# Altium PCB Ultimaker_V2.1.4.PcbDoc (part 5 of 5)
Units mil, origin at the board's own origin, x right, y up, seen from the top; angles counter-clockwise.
Board outline 6889.76 x 3110.24 mil, 4 copper layers (top, signal, Power, bot (thermal)), stack 67.717 mil thick; 574 components, 252 nets, 1322 pads, 511 vias.
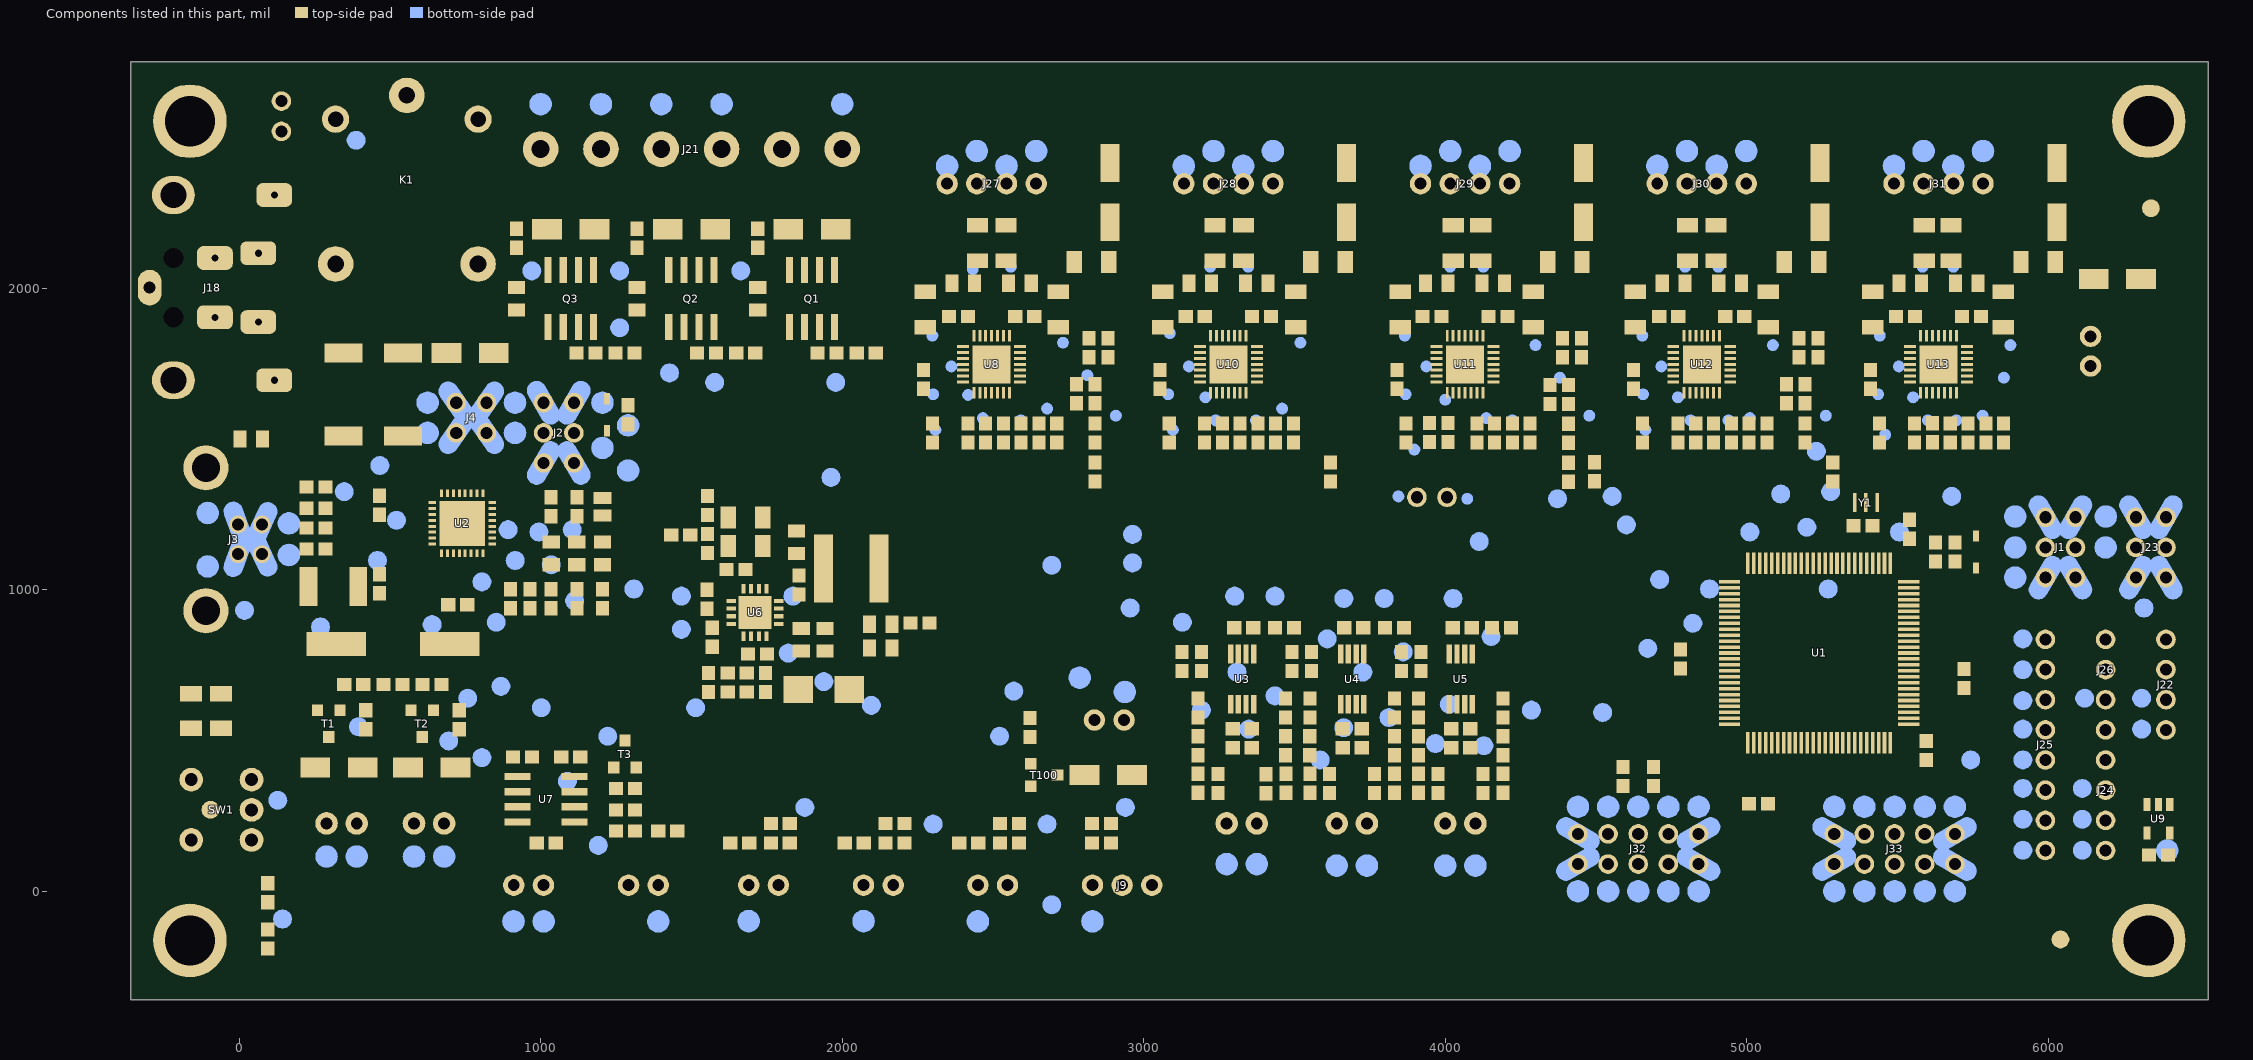
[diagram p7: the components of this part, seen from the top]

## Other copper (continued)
Power:
  rectangle net +5V: 5885.64,1527.39 5955.64,1577.39
  rectangle net +5V: 5100.64,1527.39 5170.64,1577.39
  rectangle net +5V: 4315.64,1527.39 4385.64,1577.39
  rectangle net +5V: 3530.64,1527.39 3600.64,1577.39
  rectangle net +5V: 2740.64,1527.39 2810.64,1577.39
  rectangle net +5V: 2161.66,656.84 2327.01,790.7
  pour cut-out: 4525.63,1332.39 4525.64,2312.39 5060.64,2312.39 5060.64,2492.39 5290.64,2492.39 5290.64,2337.39 5170.64,2337.39 5170.64,1942.39 5255.64,1942.39 5255.64,1577.39 5150.63,1577.39 5150.63,1527.39 5165.63,1527.39 5165.63,1332.39
  pour cut-out: 3740.63,1332.39 3740.64,2312.39 4275.64,2312.39 4275.64,2492.39 4505.64,2492.39 4505.64,2337.39 4385.64,2337.39 4385.64,1942.39 4470.64,1942.39 4470.64,1577.39 4365.63,1577.39 4365.63,1527.39 4380.63,1527.39 4380.63,1332.39
  pour cut-out: 2955.63,1332.39 2955.64,2312.39 3490.64,2312.39 3490.64,2492.39 3720.64,2492.39 3720.64,2337.39 3600.64,2337.39 3600.64,1978.63 3610.24,1956.69 3610.24,1578.74 3580.63,1577.39 3580.63,1527.39 3595.63,1527.39 3595.63,1332.39
  pour cut-out: 2170.64,1332.39 2170.64,2312.39 2705.64,2312.39 2705.64,2492.39 2935.64,2492.39 2935.64,2337.39 2815.64,2337.39 2815.64,1942.39 2900.64,1942.39 2900.64,1577.39 2795.64,1577.39 2795.64,1527.39 2810.64,1527.39 2810.64,1332.39
  region net GND: 3221.64,1927.39 3221.64,1813.39 3355.64,1813.39 3355.64,1802.39 3435.28,1801.42 3434.64,1663.39 3476.64,1663.39 3478.58,1789.61 3502.2,1789.61 3502.2,1836.85 3466.77,1836.85 3435.28,1801.42 3355.64,1802.39 3355.64,1813.39 3339.64,1813.39 3339.64,1928.39 3506.63,1928.39 3506.63,2477.39 3705.64,2477.39 3705.64,2352.39 3585.64,2352.39 3585.64,1592.39 3442.64,1592.39 3443.15,1612.44 3411.65,1643.94 3309.29,1643.94 3289.61,1628.19 3179.37,1628.19 3179.37,1580.94 3155.75,1557.32 3112.44,1557.32 3112.44,1510.08 3155.75,1510.08 3155.75,1557.32 3179.37,1580.94 3442.64,1579.39 3442.64,1592.39 3515.64,1592.39 3515.64,1512.39 3580.64,1512.39 3580.64,1347.39 3224.64,1347.39 3224.64,1419.39 3462.64,1419.39 3462.64,1464.39 3224.64,1464.39 3224.64,1347.39 2970.64,1347.39 2970.63,2146.39 2970.64,2297.39 3063.64,2297.39 3063.63,2293.39 3063.63,1814.39 2994.64,1814.39 2994.64,1757.39 3063.64,1757.39 3063.64,1583.39 3105.64,1583.39 3104.57,1643.94 3136.06,1643.94 3136.06,1828.98 3104.57,1860.47 3104.57,1927.4
  region net GND: 2436.64,1927.39 2436.64,1813.39 2570.64,1813.39 2570.64,1793.39 2642.64,1793.39 2642.64,1681.39 2686.64,1681.39 2686.64,1707.39 2799.64,1707.39 2799.64,1747.39 2755.64,1747.39 2755.64,1707.39 2686.64,1707.39 2687.24,1789.61 2718.74,1789.61 2718.74,1836.85 2687.24,1836.85 2643.94,1793.54 2570.64,1793.39 2570.64,1813.39 2554.64,1813.39 2554.64,1927.39 2721.64,1927.39 2721.64,2477.39 2920.64,2477.39 2920.64,2352.39 2800.64,2352.39 2800.64,1927.39 2885.64,1927.39 2885.64,1592.39 2658.64,1592.39 2659.69,1616.38 2632.13,1643.94 2525.83,1643.94 2506.14,1628.19 2395.91,1628.19 2395.91,1577.01 2372.28,1557.32 2325.04,1557.32 2325.04,1510.08 2372.28,1510.08 2372.28,1557.32 2395.91,1577.01 2659.69,1577.01 2658.64,1592.39 2725.64,1592.39 2725.64,1512.39 2795.64,1512.39 2795.64,1347.39 2439.64,1347.39 2439.64,1419.39 2677.64,1419.39 2677.64,1464.39 2439.64,1464.39 2439.64,1347.39 2185.64,1347.39 2185.64,2297.39 2278.64,2297.39 2278.63,1814.39 2209.64,1814.39 2209.64,1757.39 2278.64,1757.39 2278.64,1584.39 2320.64,1584.39 2321.1,1643.94 2352.6,1643.94 2352.6,1828.98 2321.1,1856.54 2320.64,1927.39
  region net GND: 4791.64,1927.39 4791.64,1813.39 4925.64,1813.39 4925.64,1793.39 4997.64,1793.39 4997.64,1681.39 5041.64,1681.39 5041.64,1707.39 5154.64,1707.39 5154.63,1748.39 5110.63,1748.39 5110.64,1707.39 5041.64,1707.39 5041.57,1789.61 5073.07,1789.61 5073.07,1836.85 5037.64,1836.85 4998.27,1793.54 4925.64,1793.39 4925.64,1813.39 4909.64,1813.39 4909.64,1928.39 5076.63,1928.39 5076.63,2477.39 5275.64,2477.39 5275.64,2352.39 5155.64,2352.39 5155.64,1927.39 5240.64,1927.39 5240.64,1592.39 5084.88,1592.76 5014.02,1592.76 5014.02,1612.44 5010.08,1616.38 4982.52,1643.94 4868.35,1643.94 4844.72,1628.19 4750.24,1628.19 4750.24,1577.01 5014.02,1577.01 5014.02,1592.76 5084.88,1592.76 5085.64,1512.39 5150.64,1512.39 5151.64,1347.39 4794.64,1347.39 4794.64,1419.39 5032.64,1419.39 5032.64,1464.39 4794.64,1464.39 4794.64,1347.39 4540.64,1347.39 4540.63,2146.39 4540.64,2297.39 4633.64,2297.39 4633.63,1814.39 4564.64,1814.39 4564.64,1757.39 4633.64,1757.39 4633.64,1584.39 4675.43,1584.88 4679.37,1557.32 4679.37,1510.08 4726.61,1510.08 4726.61,1557.32 4679.37,1557.32 4675.43,1584.88 4675.43,1643.94 4706.93,1643.94 4706.93,1828.98 4675.43,1860.47 4675.64,1927.39
  pour cut-out: 5310.63,1374.16 5310.64,2312.39 5845.64,2312.39 5845.64,2492.39 6075.64,2492.39 6075.64,2337.39 5955.64,2337.39 5955.64,1942.39 6040.64,1942.39 6040.64,1577.39 5935.63,1577.39 5935.63,1527.39 5950.63,1527.39 5950.63,1332.39 5417.56,1334.01 5417.56,1373.38
  region net GND: 4006.64,1927.39 4006.64,1813.39 4140.64,1813.39 4140.64,1793.39 4212.64,1793.39 4212.64,1681.39 4256.64,1681.39 4256.64,1707.39 4369.64,1707.39 4369.63,1748.39 4325.63,1748.39 4325.64,1707.39 4256.64,1707.39 4258.11,1789.61 4285.67,1789.61 4285.67,1836.85 4242.36,1836.85 4242.36,1793.54 4140.64,1793.39 4140.64,1813.39 4124.64,1813.39 4124.64,1928.39 4291.63,1928.39 4291.63,2477.39 4490.64,2477.39 4490.64,2352.39 4370.64,2352.39 4370.64,1927.39 4455.64,1927.39 4455.64,1592.39 4226.64,1592.39 4226.61,1608.5 4191.18,1643.94 4124.25,1643.94 4100.63,1620.31 3974.65,1620.31 3974.65,1573.07 4029.76,1573.07 4029.76,1514.02 4082.92,1515.11 4082.92,1574.17 4224.65,1574.17 4226.64,1578.39 4226.64,1592.39 4300.64,1592.39 4300.64,1512.39 4365.64,1512.39 4366.64,1347.39 3984.49,1349.76 3984.25,1417.32 4248.03,1417.32 4247.64,1464.39 3846.46,1464.57 3846.46,1417.32 3893.7,1417.32 3893.7,1464.57 3984.25,1464.57 3984.49,1349.76 3755.64,1347.39 3755.63,2146.39 3755.64,2297.39 3848.64,2297.39 3848.63,1814.39 3779.64,1814.39 3779.64,1757.39 3848.64,1757.39 3848.64,1584.39 3890.64,1584.39 3891.97,1643.94 3919.53,1643.94 3919.53,1832.91 3891.97,1856.54 3890.64,1927.39
  region net GND: 5576.64,1927.39 5576.64,1813.39 5710.64,1813.39 5710.64,1793.39 5762.05,1797.48 5762.05,1750.24 5789.61,1750.24 5791.58,1656.84 5838.82,1656.84 5838.82,1751.33 5827.01,1751.33 5813.23,1765.98 5813.23,1789.61 5856.54,1789.61 5856.54,1836.85 5821.1,1836.85 5781.73,1797.48 5762.05,1797.48 5710.64,1793.39 5710.64,1813.39 5694.64,1813.39 5694.64,1928.39 5861.63,1928.39 5861.63,2477.39 6060.64,2477.39 6060.64,2352.39 5940.64,2352.39 5940.64,1927.39 6025.64,1927.39 6025.64,1592.39 5773.86,1592.76 5773.86,1608.5 5738.43,1643.94 5663.62,1643.94 5647.87,1628.19 5533.7,1628.19 5533.7,1580.94 5625.64,1578.39 5773.86,1577.01 5773.86,1592.76 5872.28,1592.76 5872.28,1514.02 5935.64,1512.39 5936.64,1347.39 5578.98,1345.82 5579.64,1419.39 5817.64,1419.39 5817.64,1464.39 5579.64,1464.39 5578.98,1345.82 5429.37,1345.82 5429.37,1385.19 5327.01,1385.19 5325.63,2146.39 5325.64,2297.39 5418.64,2297.39 5418.63,1814.39 5349.64,1814.39 5349.64,1757.39 5418.64,1757.39 5418.64,1584.39 5466.77,1584.88 5466.77,1510.08 5510.08,1510.08 5510.08,1557.32 5466.77,1557.32 5466.77,1643.94 5490.39,1643.94 5490.39,1828.98 5462.83,1864.41 5462.83,1927.4
  pour cut-out: 792.44,2155 ccw(c792.44,2080) 717.44,2080 ccw(c792.44,2080) 792.44,2005 ccw(c792.44,2080) 867.44,2080 ccw(c792.44,2080)
  pour cut-out: 556.22,2714.06 ccw(c556.22,2639.06) 481.22,2639.06 ccw(c556.22,2639.06) 556.22,2564.06 ccw(c556.22,2639.06) 631.22,2639.06 ccw(c556.22,2639.06)
  pour cut-out: 1000,2536 ccw(c1000,2461) 925,2461 ccw(c1000,2461) 1000,2386 ccw(c1000,2461) 1075,2461 ccw(c1000,2461)
  pour cut-out: 1200,2536 ccw(c1200,2461) 1125,2461 ccw(c1200,2461) 1200,2386 ccw(c1200,2461) 1275,2461 ccw(c1200,2461)
  pour cut-out: 1400,2536 ccw(c1400,2461) 1325,2461 ccw(c1400,2461) 1400,2386 ccw(c1400,2461) 1475,2461 ccw(c1400,2461)
  pour cut-out: 1600,2536 ccw(c1600,2461) 1525,2461 ccw(c1600,2461) 1600,2386 ccw(c1600,2461) 1675,2461 ccw(c1600,2461)
  pour cut-out: 2000,2536 ccw(c2000,2461) 1925,2461 ccw(c2000,2461) 2000,2386 ccw(c2000,2461) 2075,2461 ccw(c2000,2461)
  pour cut-out: 1800,2536 ccw(c1800,2461) 1725,2461 ccw(c1800,2461) 1800,2386 ccw(c1800,2461) 1875,2461 ccw(c1800,2461)
  pour cut-out: -160,1908.15 cw(c-60,1908.15) -60,2008.15 165,2008.15 215,2058.15 215,2088.15 cw(c315,2088.15) 315,2188.15 325,2188.15 cw(c325,2088.15) 425,2088.15 425,2001.43 cw(c356.72,2001.43) 405,1953.15 279.29,1827.44 cw(c208.58,1898.15) 208.58,1798.15 -60,1798.15 cw(c-60,1898.15) -160,1898.15
  text "Copper inner2 35u" at -300,3285 h196.85
bot (thermal):
  rectangle net GND: 2426.93,1677.17 2566.93,1817.17
  rectangle net GND: 3210.63,1676.53 3350.63,1816.53
  rectangle net GND: 3997.8,1677.17 4137.8,1817.17
  rectangle net GND: 4781.26,1677.17 4921.26,1817.17
  rectangle net GND: 669,1151 810,1289
  rectangle net GND: 5564.72,1677.17 5704.72,1817.17
  region net GND: 1795,1975 1955,1975 1955,1915 1795,1915
  region net GND: 1395,1975 1555,1975 1555,1915 1395,1915
  region net GND: 995,1975 1155,1975 1155,1915 995,1915
  region net GND: -150,2170 135,2170 135,2050 -150,2050
  pour cut-out: 5346.46,1887.27 ccw(c5346.46,1858.27) 5317.46,1858.27 ccw(c5346.46,1858.27) 5346.46,1829.27 ccw(c5346.46,1858.27) 5375.46,1858.27 ccw(c5346.46,1858.27)
  pour cut-out: 5346.46,1997.5 ccw(c5346.46,1968.5) 5317.46,1968.5 ccw(c5346.46,1968.5) 5346.46,1939.5 ccw(c5346.46,1968.5) 5375.46,1968.5 ccw(c5346.46,1968.5)
  pour cut-out: 5137.8,1926.64 ccw(c5137.8,1897.64) 5108.8,1897.64 ccw(c5137.8,1897.64) 5137.8,1868.64 ccw(c5137.8,1897.64) 5166.8,1897.64 ccw(c5137.8,1897.64)
  pour cut-out: 4562.99,1887.27 ccw(c4562.99,1858.27) 4533.99,1858.27 ccw(c4562.99,1858.27) 4562.99,1829.27 ccw(c4562.99,1858.27) 4591.99,1858.27 ccw(c4562.99,1858.27)
  pour cut-out: 4562.99,1993.57 ccw(c4562.99,1964.57) 4533.99,1964.57 ccw(c4562.99,1964.57) 4562.99,1935.57 ccw(c4562.99,1964.57) 4591.99,1964.57 ccw(c4562.99,1964.57)
  pour cut-out: 4358.27,1926.64 ccw(c4358.27,1897.64) 4329.27,1897.64 ccw(c4358.27,1897.64) 4358.27,1868.64 ccw(c4358.27,1897.64) 4387.27,1897.64 ccw(c4358.27,1897.64)
  pour cut-out: 3779.53,1887.27 ccw(c3779.53,1858.27) 3750.53,1858.27 ccw(c3779.53,1858.27) 3779.53,1829.27 ccw(c3779.53,1858.27) 3808.53,1858.27 ccw(c3779.53,1858.27)
  pour cut-out: 3783.46,2005.38 ccw(c3783.46,1976.38) 3754.46,1976.38 ccw(c3783.46,1976.38) 3783.46,1947.38 ccw(c3783.46,1976.38) 3812.46,1976.38 ccw(c3783.46,1976.38)
  pour cut-out: 3574.44,1925.39 ccw(c3574.44,1896.39) 3545.44,1896.39 ccw(c3574.44,1896.39) 3574.44,1867.39 ccw(c3574.44,1896.39) 3603.44,1896.39 ccw(c3574.44,1896.39)
  pour cut-out: 2992.13,1997.5 ccw(c2992.13,1968.5) 2963.13,1968.5 ccw(c2992.13,1968.5) 2992.13,1939.5 ccw(c2992.13,1968.5) 3021.13,1968.5 ccw(c2992.13,1968.5)
  pour cut-out: 2992.13,1887.27 ccw(c2992.13,1858.27) 2963.13,1858.27 ccw(c2992.13,1858.27) 2992.13,1829.27 ccw(c2992.13,1858.27) 3021.13,1858.27 ccw(c2992.13,1858.27)
  pour cut-out: 2791.34,1926.64 ccw(c2791.34,1897.64) 2762.34,1897.64 ccw(c2791.34,1897.64) 2791.34,1868.64 ccw(c2791.34,1897.64) 2820.34,1897.64 ccw(c2791.34,1897.64)
  pour cut-out: 2205.95,1888.39 ccw(c2205.95,1859.39) 2176.95,1859.39 ccw(c2205.95,1859.39) 2205.95,1830.39 ccw(c2205.95,1859.39) 2234.95,1859.39 ccw(c2205.95,1859.39)
  pour cut-out: 2205.95,1996.15 ccw(c2205.95,1967.15) 2176.95,1967.15 ccw(c2205.95,1967.15) 2205.95,1938.15 ccw(c2205.95,1967.15) 2234.95,1967.15 ccw(c2205.95,1967.15)
  pour cut-out: -160,1908.15 cw(c-60,1908.15) -60,2008.15 165,2008.15 215,2058.15 215,2088.15 cw(c315,2088.15) 315,2188.15 325,2188.15 cw(c325,2088.15) 425,2088.15 425,2001.43 cw(c356.72,2001.43) 405,1953.15 279.29,1827.44 cw(c208.58,1898.15) 208.58,1798.15 -60,1798.15 cw(c-60,1898.15) -160,1898.15
  pour cut-out: 556.22,2714.06 ccw(c556.22,2639.06) 481.22,2639.06 ccw(c556.22,2639.06) 556.22,2564.06 ccw(c556.22,2639.06) 631.22,2639.06 ccw(c556.22,2639.06)
  pour cut-out: 925,2461 ccw(c1000,2461) 1000,2386 ccw(c1000,2461) 1075,2461 1075,2591 ccw(c1000,2591) 1000,2666 ccw(c1000,2591) 925,2591
  pour cut-out: 1125,2461 ccw(c1200,2461) 1200,2386 ccw(c1200,2461) 1275,2461 1275,2591 ccw(c1200,2591) 1200,2666 ccw(c1200,2591) 1125,2591
  pour cut-out: 1325,2461 ccw(c1400,2461) 1400,2386 ccw(c1400,2461) 1475,2461 1475,2591 ccw(c1400,2591) 1400,2666 ccw(c1400,2591) 1325,2591
  pour cut-out: 1525,2461 ccw(c1600,2461) 1600,2386 ccw(c1600,2461) 1675,2461 1675,2591 ccw(c1600,2591) 1600,2666 ccw(c1600,2591) 1525,2591
  pour cut-out: 1925,2461 ccw(c2000,2461) 2000,2386 ccw(c2000,2461) 2075,2461 2075,2591 ccw(c2000,2591) 2000,2666 ccw(c2000,2591) 1925,2591
  pour cut-out: 1800,2536 ccw(c1800,2461) 1725,2461 ccw(c1800,2461) 1800,2386 ccw(c1800,2461) 1875,2461 ccw(c1800,2461)
  pour cut-out: 792.44,2155 ccw(c792.44,2080) 717.44,2080 ccw(c792.44,2080) 792.44,2005 ccw(c792.44,2080) 867.44,2080 ccw(c792.44,2080)
  pour cut-out: 2293,2307 ccw(c2343,2307) 2343,2257 2648,2257 ccw(c2648,2307) 2698,2307 2698,2457 ccw(c2643,2457) 2643,2512 2348,2512 ccw(c2348,2457) 2293,2457
  pour cut-out: 3078,2307 ccw(c3128,2307) 3128,2257 3433,2257 ccw(c3433,2307) 3483,2307 3483,2457 ccw(c3428,2457) 3428,2512 3133,2512 ccw(c3133,2457) 3078,2457
  pour cut-out: 3863,2307 ccw(c3913,2307) 3913,2257 4218,2257 ccw(c4218,2307) 4268,2307 4268,2457 ccw(c4213,2457) 4213,2512 3918,2512 ccw(c3918,2457) 3863,2457
  pour cut-out: 4648,2307 ccw(c4698,2307) 4698,2257 5003,2257 ccw(c5003,2307) 5053,2307 5053,2457 ccw(c4998,2457) 4998,2512 4703,2512 ccw(c4703,2457) 4648,2457
  pour cut-out: 5433,2307 ccw(c5483,2307) 5483,2257 5788,2257 ccw(c5788,2307) 5838,2307 5838,2457 ccw(c5783,2457) 5783,2512 5488,2512 ccw(c5488,2457) 5433,2457
  pour cut-out: 5939.64,2436.39 ccw(c5939.64,2407.39) 5910.64,2407.39 ccw(c5939.64,2407.39) 5939.64,2378.39 ccw(c5939.64,2407.39) 5968.64,2407.39 ccw(c5939.64,2407.39)
  pour cut-out: 5903.35,2185.84 ccw(c5903.35,2156.84) 5874.35,2156.84 ccw(c5903.35,2156.84) 5903.35,2127.84 ccw(c5903.35,2156.84) 5932.35,2156.84 ccw(c5903.35,2156.84)
  pour cut-out: 5781.3,2166.16 ccw(c5781.3,2137.16) 5752.3,2137.16 ccw(c5781.3,2137.16) 5781.3,2108.16 ccw(c5781.3,2137.16) 5810.3,2137.16 ccw(c5781.3,2137.16)
  pour cut-out: 5776.64,1882.39 ccw(c5776.64,1853.39) 5747.64,1853.39 ccw(c5776.64,1853.39) 5776.64,1824.39 ccw(c5776.64,1853.39) 5805.64,1853.39 ccw(c5776.64,1853.39)
  pour cut-out: 5917.63,1925.39 ccw(c5917.63,1896.39) 5888.63,1896.39 ccw(c5917.63,1896.39) 5917.63,1867.39 ccw(c5917.63,1896.39) 5946.63,1896.39 ccw(c5917.63,1896.39)
  pour cut-out: 5910.64,1516.39 ccw(c5910.64,1487.39) 5881.64,1487.39 ccw(c5910.64,1487.39) 5910.64,1458.39 ccw(c5910.64,1487.39) 5939.64,1487.39 ccw(c5910.64,1487.39)
  pour cut-out: 5452.64,1455.39 ccw(c5452.64,1426.39) 5423.64,1426.39 ccw(c5452.64,1426.39) 5452.64,1397.39 ccw(c5452.64,1426.39) 5481.64,1426.39 ccw(c5452.64,1426.39)
  pour cut-out: 5365.64,1506.39 ccw(c5365.64,1477.39) 5336.64,1477.39 ccw(c5365.64,1477.39) 5365.64,1448.39 ccw(c5365.64,1477.39) 5394.64,1477.39 ccw(c5365.64,1477.39)
  pour cut-out: 5365.64,1616.39 ccw(c5365.64,1587.39) 5336.64,1587.39 ccw(c5365.64,1587.39) 5365.64,1558.39 ccw(c5365.64,1587.39) 5394.64,1587.39 ccw(c5365.64,1587.39)
  pour cut-out: 5494.64,1882.39 ccw(c5494.64,1853.39) 5465.64,1853.39 ccw(c5494.64,1853.39) 5494.64,1824.39 ccw(c5494.64,1853.39) 5523.64,1853.39 ccw(c5494.64,1853.39)
  pour cut-out: 5365.64,2135.39 ccw(c5365.64,2106.39) 5336.64,2106.39 ccw(c5365.64,2106.39) 5365.64,2077.39 ccw(c5365.64,2106.39) 5394.64,2106.39 ccw(c5365.64,2106.39)
  pour cut-out: 5497.84,2162.22 ccw(c5497.84,2133.22) 5468.84,2133.22 ccw(c5497.84,2133.22) 5497.84,2104.22 ccw(c5497.84,2133.22) 5526.84,2133.22 ccw(c5497.84,2133.22)
  pour cut-out: 5154.64,2436.39 ccw(c5154.64,2407.39) 5125.64,2407.39 ccw(c5154.64,2407.39) 5154.64,2378.39 ccw(c5154.64,2407.39) 5183.64,2407.39 ccw(c5154.64,2407.39)
  pour cut-out: 5118.35,2185.84 ccw(c5118.35,2156.84) 5089.35,2156.84 ccw(c5118.35,2156.84) 5118.35,2127.84 ccw(c5118.35,2156.84) 5147.35,2156.84 ccw(c5118.35,2156.84)
  pour cut-out: 4996.3,2166.16 ccw(c4996.3,2137.16) 4967.3,2137.16 ccw(c4996.3,2137.16) 4996.3,2108.16 ccw(c4996.3,2137.16) 5025.3,2137.16 ccw(c4996.3,2137.16)
  pour cut-out: 4991.64,1882.39 ccw(c4991.64,1853.39) 4962.64,1853.39 ccw(c4991.64,1853.39) 4991.64,1824.39 ccw(c4991.64,1853.39) 5020.64,1853.39 ccw(c4991.64,1853.39)
  pour cut-out: 5125.64,1516.39 ccw(c5125.64,1487.39) 5096.64,1487.39 ccw(c5125.64,1487.39) 5125.64,1458.39 ccw(c5125.64,1487.39) 5154.64,1487.39 ccw(c5125.64,1487.39)
  pour cut-out: 4713.64,1506.39 ccw(c4713.64,1477.39) 4684.64,1477.39 ccw(c4713.64,1477.39) 4713.64,1448.39 ccw(c4713.64,1477.39) 4742.64,1477.39 ccw(c4713.64,1477.39)
  pour cut-out: 4580.64,1506.39 ccw(c4580.64,1477.39) 4551.64,1477.39 ccw(c4580.64,1477.39) 4580.64,1448.39 ccw(c4580.64,1477.39) 4609.64,1477.39 ccw(c4580.64,1477.39)
  pour cut-out: 4580.64,1616.39 ccw(c4580.64,1587.39) 4551.64,1587.39 ccw(c4580.64,1587.39) 4580.64,1558.39 ccw(c4580.64,1587.39) 4609.64,1587.39 ccw(c4580.64,1587.39)
  pour cut-out: 4709.64,1882.39 ccw(c4709.64,1853.39) 4680.64,1853.39 ccw(c4709.64,1853.39) 4709.64,1824.39 ccw(c4709.64,1853.39) 4738.64,1853.39 ccw(c4709.64,1853.39)
  pour cut-out: 4580.64,2135.39 ccw(c4580.64,2106.39) 4551.64,2106.39 ccw(c4580.64,2106.39) 4580.64,2077.39 ccw(c4580.64,2106.39) 4609.64,2106.39 ccw(c4580.64,2106.39)
  pour cut-out: 4712.84,2162.22 ccw(c4712.84,2133.22) 4683.84,2133.22 ccw(c4712.84,2133.22) 4712.84,2104.22 ccw(c4712.84,2133.22) 4741.84,2133.22 ccw(c4712.84,2133.22)
  pour cut-out: 4369.64,2436.39 ccw(c4369.64,2407.39) 4340.64,2407.39 ccw(c4369.64,2407.39) 4369.64,2378.39 ccw(c4369.64,2407.39) 4398.64,2407.39 ccw(c4369.64,2407.39)
  pour cut-out: 4211.3,2166.16 ccw(c4211.3,2137.16) 4182.3,2137.16 ccw(c4211.3,2137.16) 4211.3,2108.16 ccw(c4211.3,2137.16) 4240.3,2137.16 ccw(c4211.3,2137.16)
  pour cut-out: 4206.64,1882.39 ccw(c4206.64,1853.39) 4177.64,1853.39 ccw(c4206.64,1853.39) 4206.64,1824.39 ccw(c4206.64,1853.39) 4235.64,1853.39 ccw(c4206.64,1853.39)
  pour cut-out: 4340.64,1516.39 ccw(c4340.64,1487.39) 4311.64,1487.39 ccw(c4340.64,1487.39) 4340.64,1458.39 ccw(c4340.64,1487.39) 4369.64,1487.39 ccw(c4340.64,1487.39)
  pour cut-out: 3795.64,1506.39 ccw(c3795.64,1477.39) 3766.64,1477.39 ccw(c3795.64,1477.39) 3795.64,1448.39 ccw(c3795.64,1477.39) 3824.64,1477.39 ccw(c3795.64,1477.39)
  pour cut-out: 3795.64,1616.39 ccw(c3795.64,1587.39) 3766.64,1587.39 ccw(c3795.64,1587.39) 3795.64,1558.39 ccw(c3795.64,1587.39) 3824.64,1587.39 ccw(c3795.64,1587.39)
  pour cut-out: 3924.64,1882.39 ccw(c3924.64,1853.39) 3895.64,1853.39 ccw(c3924.64,1853.39) 3924.64,1824.39 ccw(c3924.64,1853.39) 3953.64,1853.39 ccw(c3924.64,1853.39)
  pour cut-out: 4333.35,2185.84 ccw(c4333.35,2156.84) 4304.35,2156.84 ccw(c4333.35,2156.84) 4333.35,2127.84 ccw(c4333.35,2156.84) 4362.35,2156.84 ccw(c4333.35,2156.84)
  pour cut-out: 3927.84,2162.22 ccw(c3927.84,2133.22) 3898.84,2133.22 ccw(c3927.84,2133.22) 3927.84,2104.22 ccw(c3927.84,2133.22) 3956.84,2133.22 ccw(c3927.84,2133.22)
  pour cut-out: 3795.64,2135.39 ccw(c3795.64,2106.39) 3766.64,2106.39 ccw(c3795.64,2106.39) 3795.64,2077.39 ccw(c3795.64,2106.39) 3824.64,2106.39 ccw(c3795.64,2106.39)
  pour cut-out: 3584.64,2436.39 ccw(c3584.64,2407.39) 3555.64,2407.39 ccw(c3584.64,2407.39) 3584.64,2378.39 ccw(c3584.64,2407.39) 3613.64,2407.39 ccw(c3584.64,2407.39)
  pour cut-out: 3548.35,2185.84 ccw(c3548.35,2156.84) 3519.35,2156.84 ccw(c3548.35,2156.84) 3548.35,2127.84 ccw(c3548.35,2156.84) 3577.35,2156.84 ccw(c3548.35,2156.84)
  pour cut-out: 3426.3,2166.16 ccw(c3426.3,2137.16) 3397.3,2137.16 ccw(c3426.3,2137.16) 3426.3,2108.16 ccw(c3426.3,2137.16) 3455.3,2137.16 ccw(c3426.3,2137.16)
  pour cut-out: 3421.64,1882.39 ccw(c3421.64,1853.39) 3392.64,1853.39 ccw(c3421.64,1853.39) 3421.64,1824.39 ccw(c3421.64,1853.39) 3450.64,1853.39 ccw(c3421.64,1853.39)
  pour cut-out: 3555.64,1511.39 ccw(c3555.64,1482.39) 3526.64,1482.39 ccw(c3555.64,1482.39) 3555.64,1453.39 ccw(c3555.64,1482.39) 3584.64,1482.39 ccw(c3555.64,1482.39)
  pour cut-out: 3143.64,1506.39 ccw(c3143.64,1477.39) 3114.64,1477.39 ccw(c3143.64,1477.39) 3143.64,1448.39 ccw(c3143.64,1477.39) 3172.64,1477.39 ccw(c3143.64,1477.39)
  pour cut-out: 3010.64,1506.39 ccw(c3010.64,1477.39) 2981.64,1477.39 ccw(c3010.64,1477.39) 3010.64,1448.39 ccw(c3010.64,1477.39) 3039.64,1477.39 ccw(c3010.64,1477.39)
  pour cut-out: 3010.64,1616.39 ccw(c3010.64,1587.39) 2981.64,1587.39 ccw(c3010.64,1587.39) 3010.64,1558.39 ccw(c3010.64,1587.39) 3039.64,1587.39 ccw(c3010.64,1587.39)
  pour cut-out: 3139.64,1882.39 ccw(c3139.64,1853.39) 3110.64,1853.39 ccw(c3139.64,1853.39) 3139.64,1824.39 ccw(c3139.64,1853.39) 3168.64,1853.39 ccw(c3139.64,1853.39)
  pour cut-out: 3010.64,2135.39 ccw(c3010.64,2106.39) 2981.64,2106.39 ccw(c3010.64,2106.39) 3010.64,2077.39 ccw(c3010.64,2106.39) 3039.64,2106.39 ccw(c3010.64,2106.39)
  pour cut-out: 3142.84,2162.22 ccw(c3142.84,2133.22) 3113.84,2133.22 ccw(c3142.84,2133.22) 3142.84,2104.22 ccw(c3142.84,2133.22) 3171.84,2133.22 ccw(c3142.84,2133.22)
  pour cut-out: 2799.64,2436.39 ccw(c2799.64,2407.39) 2770.64,2407.39 ccw(c2799.64,2407.39) 2799.64,2378.39 ccw(c2799.64,2407.39) 2828.64,2407.39 ccw(c2799.64,2407.39)
  pour cut-out: 2763.35,2185.84 ccw(c2763.35,2156.84) 2734.35,2156.84 ccw(c2763.35,2156.84) 2763.35,2127.84 ccw(c2763.35,2156.84) 2792.35,2156.84 ccw(c2763.35,2156.84)
  pour cut-out: 2641.31,2166.16 ccw(c2641.31,2137.16) 2612.31,2137.16 ccw(c2641.31,2137.16) 2641.31,2108.16 ccw(c2641.31,2137.16) 2670.31,2137.16 ccw(c2641.31,2137.16)
  pour cut-out: 2636.64,1882.39 ccw(c2636.64,1853.39) 2607.64,1853.39 ccw(c2636.64,1853.39) 2636.64,1824.39 ccw(c2636.64,1853.39) 2665.64,1853.39 ccw(c2636.64,1853.39)
  pour cut-out: 2770.64,1516.39 ccw(c2770.64,1487.39) 2741.64,1487.39 ccw(c2770.64,1487.39) 2770.64,1458.39 ccw(c2770.64,1487.39) 2799.64,1487.39 ccw(c2770.64,1487.39)
  pour cut-out: 2358.64,1506.39 ccw(c2358.64,1477.39) 2329.64,1477.39 ccw(c2358.64,1477.39) 2358.64,1448.39 ccw(c2358.64,1477.39) 2387.64,1477.39 ccw(c2358.64,1477.39)
  pour cut-out: 2225.64,1506.39 ccw(c2225.64,1477.39) 2196.64,1477.39 ccw(c2225.64,1477.39) 2225.64,1448.39 ccw(c2225.64,1477.39) 2254.64,1477.39 ccw(c2225.64,1477.39)
  pour cut-out: 2225.64,1616.39 ccw(c2225.64,1587.39) 2196.64,1587.39 ccw(c2225.64,1587.39) 2225.64,1558.39 ccw(c2225.64,1587.39) 2254.64,1587.39 ccw(c2225.64,1587.39)
  pour cut-out: 2354.64,1882.39 ccw(c2354.64,1853.39) 2325.64,1853.39 ccw(c2354.64,1853.39) 2354.64,1824.39 ccw(c2354.64,1853.39) 2383.64,1853.39 ccw(c2354.64,1853.39)
  pour cut-out: 2225.64,2135.39 ccw(c2225.64,2106.39) 2196.64,2106.39 ccw(c2225.64,2106.39) 2225.64,2077.39 ccw(c2225.64,2106.39) 2254.64,2106.39 ccw(c2225.64,2106.39)
  pour cut-out: 2357.84,2162.22 ccw(c2357.84,2133.22) 2328.84,2133.22 ccw(c2357.84,2133.22) 2357.84,2104.22 ccw(c2357.84,2133.22) 2386.84,2133.22 ccw(c2357.84,2133.22)
  pour cut-out: 3881.89,1406.95 ccw(c3881.89,1377.95) 3852.89,1377.95 ccw(c3881.89,1377.95) 3881.89,1348.95 ccw(c3881.89,1377.95) 3910.89,1377.95 ccw(c3881.89,1377.95)
  text "Copper bot 70u" at -300,3010 h196.85

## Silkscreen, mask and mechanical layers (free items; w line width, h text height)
Top Overlay:
  drawing of 27 lines, arcs and shapes, not listed
  text "24V" at 85,2690 h40
  text "HEATER1" at 975,2685 h40
  text "HEATER2" at 1370,2685 h40
  text "HEATED BED" at 1705,2685 h40
  text "-" at 70,2640 h40 r180
  text "E2" at 5910,2590 h78.74
  text "X" at 2767.96,2585.98 h78.74
  text "E1" at 5126.22,2585.98 h78.74
  text "Y" at 3555.36,2582.04 h78.74
  text "Z" at 4342.76,2582.04 h78.74
  text "+" at 70,2540 h40 r180
  text "-" at 5995,1799.88 h40 r270
  text "ICSP2" at 965,1685 h40
  text "+" at 6035,1669.88 h40 r90
  text "FAN 19-24V" at 6100,1585 h40
  text "19-24Vdc" at -315,1565 h40
  text "ICSP1" at 5960,1310 h40
  text "EXT/IO" at 6225,1310 h40
  text "8/16 STEP" at 3785,1184.88 h40
  text "USB" at -310,810 h40
  text "ON" at 1225,795 h40 r90
  text "RX" at 1055,790 h40 r90
  text "TX" at 1145,790 h40 r90
  text "EXP3" at 6120,630.63 h40 r90
  text "SERIAL" at 6320,575 h40 r90
  text "FAN 5V" at 3090.79,475.74 h40 r90
  text "Ultimainboard rev. 2.1.4" at 1590,465 h40
  text "ADC1" at 5920,420 h40 r90
  text "Based on Arduino hardware" at 1590,400 h40
  text "www.ultimaker.com/umb214" at 1590,340 h40
  text "+" at 270,300 h40 r90
  text "+" at 560,300 h40 r90
  text "-" at 400,290 h40
  text "-" at 690,290 h40
  text "SW/EdB/CdB/MM" at 1590,270 h40
  text "EXP1" at 4590,270 h40
  text "EXP2" at 5435,270 h40
  text "ADC2" at 6120,260 h40 r90
  text "PWM" at 215,-155 h40 r90
  text "PWM" at 505,-155 h40 r90
  text "FAN" at 215,-310 h40 r90
  text "LED" at 505,-310 h40 r90
  text "SAFETY1" at 790,-310 h40 r90
  text "SAFETY2" at 1170,-310 h40 r90
  text "X-STOP" at 1570,-310 h40 r90
  text "Y-STOP" at 1950,-310 h40 r90
  text "Z-STOP" at 2330,-310 h40 r90
  text "ANALOG" at 2710,-310 h40 r90
  text "TEMP1" at 3206.5,-315.51 h40 r90
  text "TEMP2" at 3571.5,-315.51 h40 r90
  text "TEMP3" at 3926.5,-315.51 h40 r90
Bottom Overlay:
  drawing of 41 lines, arcs and shapes, not listed
  text "HEATER1" at 1230,2670 h40
  text "HEATER2" at 1630,2670 h40
  text "HEATED BED" at 2100,2670 h40
  text "X" at 2520,2630 h78.74
  text "Y" at 3310,2630 h78.74
  text "Z" at 4090,2630 h78.74
  text "E1" at 4910,2630 h78.74
  text "E2" at 5710,2630 h78.74
  text "-" at 150,2080 h60
  text "19-24Vdc" at 130,1980 h40
  text "+" at 150,1860 h60
  text "FAN" at 6490,1770 h40
  text "USB" at -180,1150 h40
  text "PWM" at 310,-310 h40
  text "FAN" at 450,-310 h40
  text "PWM" at 600,-310 h40
  text "LED" at 740,-310 h40
  text "SAFETY1" at 1087.87,-310 h40
  text "SAFETY2" at 1474.25,-310 h40
  text "X-STOP" at 1852.56,-310 h40
  text "Y-STOP" at 2233.62,-310 h40
  text "Z-STOP" at 2613.62,-310 h40
  text "ANALOG" at 3050,-310 h40
  text "TEMP1" at 3415,-310 h40
  text "TEMP2" at 3785,-310 h40
  text "TEMP3" at 4145,-310 h40
  text "EXP1" at 4700,-310 h40
  text "EXP2" at 5560,-310 h40
Mechanical 1:
  text "Referentie punt midden stepper driver" at 3255,2910 h60
  text "Local quiet" at 1315,965 h10
Board Outline:
  the board outline again, w7

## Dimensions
6529.76,2760.24 to 6529.76,-360 on Mechanical 1
-360,2750.24 to 6529.76,2750.24 on Mechanical 1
